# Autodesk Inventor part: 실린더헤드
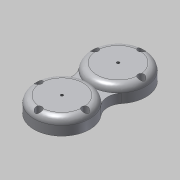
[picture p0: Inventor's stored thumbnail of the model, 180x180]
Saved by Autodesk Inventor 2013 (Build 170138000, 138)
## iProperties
Created: 2016-11
Part Number: 실린더헤드
Material: 알루미늄 6061
Document SubType Name: Modeling
Designer: mduedu
Density: 2.71 g/cm^3
Mass: 284.819 g
Surface Area: 227.25 cm^2
Volume: 105.099 cm^3
Author: mduedu
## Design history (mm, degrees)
sketch "스케치1"
  geometry: C1 r 42 at (0, 0); 1 further point
  constraints: 1 centre point, 1 coincident
  dimensions: "d0" = 84 diameter of C1
extrude "돌출1" new body sketch "스케치1" distance "d1" = 24; taper "d2" = 0 deg
fillet "모깎기1" dims "d3" = 10
sketch "스케치2"
  geometry: C1 r 30 at (0, 0); 1 further point
  constraints: 1 centre point, 1 coincident
  dimensions: "d4" = 60 diameter of C1
extrude "돌출2" join sketch "스케치2" distance "d5" = 5; taper "d6" = 0 deg
sketch "스케치3"
  geometry: C1 r 25 at (0, 0); 1 further point
  constraints: 1 centre point, 1 coincident
  dimensions: "d7" = 50 diameter of C1
extrude "돌출3" cut sketch "스케치3" distance "d8" = 20; taper "d9" = 0 deg
hole "구멍1" diameter "d12" = 4.134; stored, may be unused: countersink angle "d16" = 90 deg, drill point angle "d18" = 118 deg; dims "d10" = 10, "d11" = 10, "d13" = 6, "d14" = 4, "d15" = 2, "d17" = 8
chamfer "모따기1" distance "d19" = 1; stored, may be unused: second distance "d20" = 2, angle "d21" = 45 deg
fillet "모깎기2" dims "d22" = 3
sketch "스케치4"
  geometry: C1 r 17.5 at (0, 0); 1 further point
  constraints: 1 centre point, 1 coincident
  dimensions: "d23" = 35 diameter of C1
extrude "돌출4" cut sketch "스케치4" distance "d24" = 2; taper "d25" = 0 deg
fillet "모깎기3" dims "d26" = 0.5
sketch "스케치5" dims "d32" = 70
  geometry: C1 r 5 at (0, 35); 3 further points
  constraints: 2 coincident, 2 vertical alignment, 1 centre point, 2 other
  dimensions: "d33" = 10 diameter of C1
extrude "돌출5" cut sketch "스케치5" distance "d34" = 10; taper "d35" = 0 deg
sketch "스케치6"
  geometry: A1 r 35 centre (0, -35) between (0, 0) and (-35, -35); 2 further points
  constraints: 3 point on circle, 2 horizontal alignment, 1 centre point, 1 coincident, 1 vertical alignment
  dimensions: "d39" = 70 diameter of A1
hole "구멍3" sketch "스케치6" at (0, 0), (-35, -35), (35, -35) diameter "d57" = 5.5; stored, may be unused: countersink angle "d61" = 90 deg, drill point angle "d63" = 118 deg; dims "d58" = 6, "d59" = 4, "d60" = 2, "d62" = 8
chamfer "모따기2" distance "d54" = 5; stored, may be unused: second distance "d55" = 2, angle "d56" = 30 deg
node "작업 평면1"
sketch "스케치8"
  geometry: L1 (0, 85)-(0, 0); A1 r 42 centre (0, 85) between (-32.469, 58.358) and (32.469, 58.358) reference; A2 r 42 centre (0, 0) between (-32.469, 26.642) and (32.469, 26.642) reference; A3 r 25 centre (51.795, 42.5) between (32.469, 26.642) and (32.469, 58.358); A4 r 25 centre (-51.795, 42.5) between (-32.469, 58.358) and (-32.469, 26.642); A5 r 25 centre (-51.795, 42.5) between (-32.469, 26.642) and (-32.469, 58.358); A6 r 25 centre (51.795, 42.5) between (32.469, 58.358) and (32.469, 26.642); A7 r 42 centre (0, 85) between (-32.469, 58.358) and (32.469, 58.358); A8 r 42 centre (0, 0) between (32.469, 26.642) and (-32.469, 26.642); 1 further point
  constraints: 16 point on circle, 6 centre point, 2 coincident, 2 end point, 2 tangent, 1 symmetric about line, 1 vertical, 1 other
  dimensions: "d65" = 50 diameter of A3
extrude "돌출6" join sketch "스케치8" distance "d67" = 14; taper "d68" = 0 deg
node "솔리드1"
pattern_circular "원형 패턴1" dims angle "d37" = 360 deg
mirror "대칭1"
other parameters: "d64" = 42.5
